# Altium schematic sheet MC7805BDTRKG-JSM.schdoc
size 127 x 101 mm
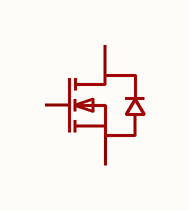
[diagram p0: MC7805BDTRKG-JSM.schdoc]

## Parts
U?  mc7805bdtrkg-jsm  [TO-252-2_L6.6-W6.1-P4.58-LS9.9-TL]  (value not drawn)

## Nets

Not connected (* = marked no-connect by the designer): U? 1(G) 2(D) 3(S)

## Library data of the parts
U? = mc7805bdtrkg-jsm: 输出极性:正极;工作电压:25V;输出电压:5V;输出电流:1.5A;电源纹波抑制比(PSRR):80dB@(120Hz);输出类型:固定;; Manufacturer: JSMSEMI(杰盛微); AddInBom: yes; ModelId: ce57f84d66384067af8a68020b6de06d; ModelName: TO-252-2L-3P_L6.6-W6.1-H2.3-LS10.1-P4.6; ModelTransform: 259.842,390.52442,0,270,0,0,39.372,0.002,0; Output Configuration: 正极; Voltage - Supply: 25V; Output Voltage: 5V; Output Current: 1.5A; Voltage Dropout: 2V; standby current: 8mA; Noise: 40uVrms; Output Type: 固定; Number of Outputs: 1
